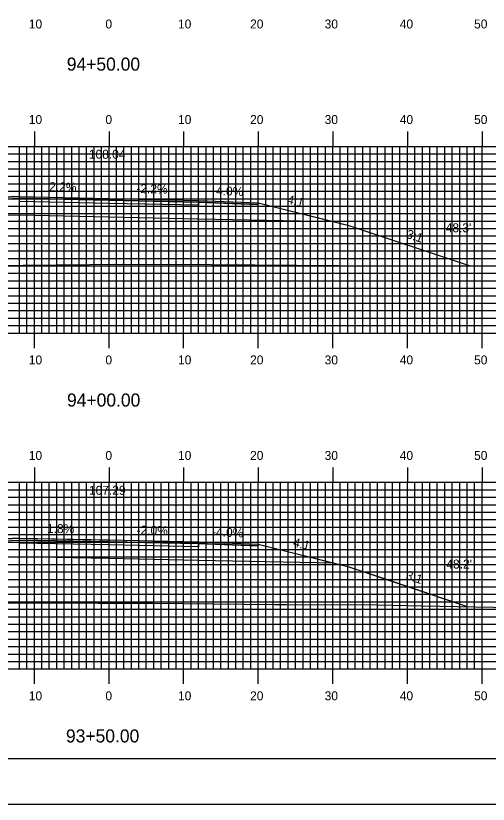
# Model space of a CAD drawing. Extents: x 1765333 to 1765676, y 442591 to 442811.
# Drawn here: x 1765485.9 to 1765549.2, y 442590.5 to 442696.2 of the extents above; entities that cross this region are included whole.
import ezdxf

# ---------------------------------------------------------------- set-up
doc = ezdxf.new("R2010")
doc.units = 0
for name, color, linetype in [('ANNOTATION', 7, 'Continuous'), ('BORDER', 7, 'Continuous'), ('D_Roadway_Centerline', 7, 'Continuous'), ('D_Roadway_Centerline_Text', 7, 'Continuous'), ('D_Roadway_Edge_Shoulder', 7, 'Continuous'), ('D_Roadway_Edge_TW', 7, 'Continuous'), ('D_Roadway_Pavement', 7, 'Continuous'), ('D_Roadway_SlopeLines', 7, 'Continuous'), ('D_Roadway_SubGrade', 7, 'Continuous'), ('D_Text_Standard', 7, 'Continuous'), ('H_V ANNOTATION', 7, 'Continuous'), ('MAJOR', 7, 'Continuous'), ('MINOR', 7, 'Continuous'), ('PLOT BOUNDARY', 7, 'Continuous'), ('S_Roadway_Centerline', 7, 'Continuous')]:
    doc.layers.add(name, color=color, linetype=linetype)

msp = doc.modelspace()

# ---------------------------------------------------------------- linework, layer by layer
at = {"layer": 'BORDER'}
msp.add_lwpolyline([(1765348.77, 442596.67), (1765668.77, 442596.67), (1765668.77, 442806.67), (1765348.77, 442806.67)], close=True, dxfattribs=at)
at = {"layer": 'D_Roadway_Centerline'}
for points in [[(1765447.79, 442662.46), (1765466.37, 442668.65), (1765466.37, 442668.65), (1765466.86, 442668.77), (1765468.2, 442669.11), (1765468.2, 442669.11), (1765473.59, 442670.45), (1765478.37, 442671.65), (1765478.37, 442671.65), (1765486.37, 442671.97), (1765486.38, 442671.97), (1765498.37, 442671.71), (1765510.37, 442671.44), (1765518.37, 442671.12), (1765518.37, 442671.12), (1765526.92, 442668.98), (1765528.55, 442668.58), (1765529.56, 442668.32), (1765530.37, 442668.12), (1765546.65, 442662.7), (1765546.65, 442662.7)], [(1765449.22, 442617.13), (1765449.22, 442617.13), (1765460.52, 442620.9), (1765466.36, 442622.84), (1765466.37, 442622.85), (1765466.37, 442622.85), (1765468.2, 442623.3), (1765468.2, 442623.3), (1765472.08, 442624.28), (1765478.37, 442625.85), (1765486.37, 442626.17), (1765497.05, 442625.98), (1765498.37, 442625.96), (1765510.36, 442625.72), (1765510.37, 442625.72), (1765518.36, 442625.4), (1765518.37, 442625.4), (1765528.54, 442622.85), (1765528.54, 442622.85), (1765528.96, 442622.75), (1765530.37, 442622.4), (1765535.39, 442620.72), (1765546.52, 442617.01)]]:
    msp.add_lwpolyline(points, dxfattribs=at)
at = {"layer": 'D_Roadway_Edge_Shoulder'}
for points in [[(1765486.37, 442671.97), (1765478.37, 442671.65), (1765478.37, 442671.4), (1765486.37, 442671.72)], [(1765510.37, 442671.44), (1765518.37, 442671.12), (1765518.37, 442670.87), (1765510.37, 442671.19)], [(1765486.37, 442626.17), (1765478.37, 442625.85), (1765478.37, 442625.6), (1765486.37, 442625.92)], [(1765510.37, 442625.72), (1765518.37, 442625.4), (1765518.37, 442625.15), (1765510.37, 442625.47)]]:
    msp.add_lwpolyline(points, close=True, dxfattribs=at)
at = {"layer": 'D_Roadway_Edge_TW'}
for points in [[(1765486.37, 442671.72), (1765486.37, 442671.97), (1765498.37, 442671.71), (1765510.37, 442671.44), (1765510.37, 442671.19), (1765498.37, 442671.46)], [(1765486.37, 442625.92), (1765486.37, 442626.17), (1765498.37, 442625.96), (1765510.37, 442625.72), (1765510.37, 442625.47), (1765498.37, 442625.71)]]:
    msp.add_lwpolyline(points, close=True, dxfattribs=at)
at = {"layer": 'D_Roadway_Pavement'}
for points in [[(1765486.37, 442671.3), (1765486.37, 442671.72), (1765498.37, 442671.46), (1765510.37, 442671.19), (1765510.37, 442670.78), (1765498.37, 442671.04)], [(1765486.37, 442625.5), (1765486.37, 442625.92), (1765498.37, 442625.71), (1765510.37, 442625.47), (1765510.37, 442625.05), (1765498.37, 442625.29)]]:
    msp.add_lwpolyline(points, close=True, dxfattribs=at)
at = {"layer": 'D_Roadway_SlopeLines'}
for points in [[(1765518.37, 442671.12), (1765530.37, 442668.12), (1765546.65, 442662.7)], [(1765518.37, 442625.4), (1765530.37, 442622.4), (1765546.52, 442617.01)]]:
    msp.add_lwpolyline(points, dxfattribs=at)
at = {"layer": 'D_Roadway_SubGrade'}
for points in [[(1765486.37, 442669.47), (1765468.2, 442669.11), (1765478.37, 442671.65), (1765478.37, 442671.4), (1765486.37, 442671.72), (1765498.37, 442671.46), (1765510.37, 442671.19), (1765518.37, 442670.87), (1765518.37, 442671.12), (1765528.55, 442668.58), (1765510.37, 442668.94), (1765498.37, 442669.21)], [(1765486.37, 442623.67), (1765468.2, 442623.3), (1765478.37, 442625.85), (1765478.37, 442625.6), (1765486.37, 442625.92), (1765498.37, 442625.71), (1765510.37, 442625.47), (1765518.37, 442625.15), (1765518.37, 442625.4), (1765528.54, 442622.85), (1765510.37, 442623.22), (1765498.37, 442623.46)]]:
    msp.add_lwpolyline(points, close=True, dxfattribs=at)
at = {"layer": 'MAJOR'}
for p, q in [((1765488.37, 442680.67), (1765488.37, 442678.67)), ((1765498.37, 442680.67), (1765498.37, 442678.67)), ((1765508.37, 442680.67), (1765508.37, 442678.67)), ((1765518.37, 442680.67), (1765518.37, 442678.67)), ((1765528.37, 442680.67), (1765528.37, 442678.67)), ((1765538.37, 442680.67), (1765538.37, 442678.67)), ((1765548.37, 442680.67), (1765548.37, 442678.67)), ((1765358.37, 442678.67), (1765638.37, 442678.67)), ((1765358.37, 442678.67), (1765638.37, 442678.67)), ((1765488.37, 442653.67), (1765488.37, 442678.67)), ((1765498.37, 442653.67), (1765498.37, 442678.67)), ((1765508.37, 442653.67), (1765508.37, 442678.67)), ((1765518.37, 442653.67), (1765518.37, 442678.67)), ((1765528.37, 442653.67), (1765528.37, 442678.67)), ((1765538.37, 442653.67), (1765538.37, 442678.67)), ((1765548.37, 442653.67), (1765548.37, 442678.67)), ((1765358.37, 442673.67), (1765638.37, 442673.67)), ((1765358.37, 442668.67), (1765638.37, 442668.67)), ((1765358.37, 442663.67), (1765638.37, 442663.67)), ((1765358.37, 442658.67), (1765638.37, 442658.67)), ((1765358.37, 442653.67), (1765638.37, 442653.67)), ((1765358.37, 442653.67), (1765638.37, 442653.67)), ((1765488.37, 442651.66), (1765488.37, 442653.67)), ((1765498.37, 442651.66), (1765498.37, 442653.67)), ((1765508.37, 442651.66), (1765508.37, 442653.67)), ((1765518.37, 442651.66), (1765518.37, 442653.67)), ((1765528.37, 442651.66), (1765528.37, 442653.67)), ((1765538.37, 442651.66), (1765538.37, 442653.67)), ((1765548.37, 442651.66), (1765548.37, 442653.67)), ((1765488.37, 442635.67), (1765488.37, 442633.67)), ((1765498.37, 442635.67), (1765498.37, 442633.67)), ((1765508.37, 442635.67), (1765508.37, 442633.67)), ((1765518.37, 442635.67), (1765518.37, 442633.67)), ((1765528.37, 442635.67), (1765528.37, 442633.67)), ((1765538.37, 442635.67), (1765538.37, 442633.67)), ((1765548.37, 442635.67), (1765548.37, 442633.67)), ((1765358.37, 442633.67), (1765638.37, 442633.67)), ((1765358.37, 442633.67), (1765638.37, 442633.67)), ((1765488.37, 442608.67), (1765488.37, 442633.67)), ((1765498.37, 442608.67), (1765498.37, 442633.67)), ((1765508.37, 442608.67), (1765508.37, 442633.67)), ((1765518.37, 442608.67), (1765518.37, 442633.67)), ((1765528.37, 442608.67), (1765528.37, 442633.67)), ((1765538.37, 442608.67), (1765538.37, 442633.67)), ((1765548.37, 442608.67), (1765548.37, 442633.67)), ((1765358.37, 442628.67), (1765638.37, 442628.67)), ((1765358.37, 442623.67), (1765638.37, 442623.67)), ((1765358.37, 442618.67), (1765638.37, 442618.67)), ((1765358.37, 442613.67), (1765638.37, 442613.67)), ((1765358.37, 442608.67), (1765638.37, 442608.67)), ((1765358.37, 442608.67), (1765638.37, 442608.67)), ((1765488.37, 442606.66), (1765488.37, 442608.67)), ((1765498.37, 442606.66), (1765498.37, 442608.67)), ((1765508.37, 442606.66), (1765508.37, 442608.67)), ((1765518.37, 442606.66), (1765518.37, 442608.67)), ((1765528.37, 442606.66), (1765528.37, 442608.67)), ((1765538.37, 442606.66), (1765538.37, 442608.67)), ((1765548.37, 442606.66), (1765548.37, 442608.67))]:
    msp.add_line(p, q, dxfattribs=at)
at = {"layer": 'MINOR'}
for p, q in [((1765486.37, 442653.67), (1765486.37, 442678.67)), ((1765487.37, 442653.67), (1765487.37, 442678.67)), ((1765489.37, 442653.67), (1765489.37, 442678.67)), ((1765490.37, 442653.67), (1765490.37, 442678.67)), ((1765491.37, 442653.67), (1765491.37, 442678.67)), ((1765492.37, 442653.67), (1765492.37, 442678.67)), ((1765493.37, 442653.67), (1765493.37, 442678.67)), ((1765494.37, 442653.67), (1765494.37, 442678.67)), ((1765495.37, 442653.67), (1765495.37, 442678.67)), ((1765496.37, 442653.67), (1765496.37, 442678.67)), ((1765497.37, 442653.67), (1765497.37, 442678.67)), ((1765499.37, 442653.67), (1765499.37, 442678.67)), ((1765500.37, 442653.67), (1765500.37, 442678.67)), ((1765501.37, 442653.67), (1765501.37, 442678.67)), ((1765502.37, 442653.67), (1765502.37, 442678.67)), ((1765503.37, 442653.67), (1765503.37, 442678.67)), ((1765504.37, 442653.67), (1765504.37, 442678.67)), ((1765505.37, 442653.67), (1765505.37, 442678.67)), ((1765506.37, 442653.67), (1765506.37, 442678.67)), ((1765507.37, 442653.67), (1765507.37, 442678.67)), ((1765509.37, 442653.67), (1765509.37, 442678.67)), ((1765510.37, 442653.67), (1765510.37, 442678.67)), ((1765511.37, 442653.67), (1765511.37, 442678.67)), ((1765512.37, 442653.67), (1765512.37, 442678.67)), ((1765513.37, 442653.67), (1765513.37, 442678.67)), ((1765514.37, 442653.67), (1765514.37, 442678.67)), ((1765515.37, 442653.67), (1765515.37, 442678.67)), ((1765516.37, 442653.67), (1765516.37, 442678.67)), ((1765517.37, 442653.67), (1765517.37, 442678.67)), ((1765519.37, 442653.67), (1765519.37, 442678.67)), ((1765520.37, 442653.67), (1765520.37, 442678.67)), ((1765521.37, 442653.67), (1765521.37, 442678.67)), ((1765522.37, 442653.67), (1765522.37, 442678.67)), ((1765523.37, 442653.67), (1765523.37, 442678.67)), ((1765524.37, 442653.67), (1765524.37, 442678.67)), ((1765525.37, 442653.67), (1765525.37, 442678.67)), ((1765526.37, 442653.67), (1765526.37, 442678.67)), ((1765527.37, 442653.67), (1765527.37, 442678.67)), ((1765529.37, 442653.67), (1765529.37, 442678.67)), ((1765530.37, 442653.67), (1765530.37, 442678.67)), ((1765531.37, 442653.67), (1765531.37, 442678.67)), ((1765532.37, 442653.67), (1765532.37, 442678.67)), ((1765533.37, 442653.67), (1765533.37, 442678.67)), ((1765534.37, 442653.67), (1765534.37, 442678.67)), ((1765535.37, 442653.67), (1765535.37, 442678.67)), ((1765536.37, 442653.67), (1765536.37, 442678.67)), ((1765537.37, 442653.67), (1765537.37, 442678.67)), ((1765539.37, 442653.67), (1765539.37, 442678.67)), ((1765540.37, 442653.67), (1765540.37, 442678.67)), ((1765541.37, 442653.67), (1765541.37, 442678.67)), ((1765542.37, 442653.67), (1765542.37, 442678.67)), ((1765543.37, 442653.67), (1765543.37, 442678.67)), ((1765544.37, 442653.67), (1765544.37, 442678.67)), ((1765545.37, 442653.67), (1765545.37, 442678.67)), ((1765546.37, 442653.67), (1765546.37, 442678.67)), ((1765547.37, 442653.67), (1765547.37, 442678.67)), ((1765358.37, 442677.67), (1765638.37, 442677.67)), ((1765358.37, 442676.67), (1765638.37, 442676.67)), ((1765358.37, 442675.67), (1765638.37, 442675.67)), ((1765358.37, 442674.67), (1765638.37, 442674.67)), ((1765358.37, 442672.67), (1765638.37, 442672.67)), ((1765358.37, 442671.67), (1765638.37, 442671.67)), ((1765358.37, 442670.67), (1765638.37, 442670.67)), ((1765358.37, 442669.67), (1765638.37, 442669.67)), ((1765358.37, 442667.67), (1765638.37, 442667.67)), ((1765358.37, 442666.67), (1765638.37, 442666.67)), ((1765358.37, 442665.67), (1765638.37, 442665.67)), ((1765358.37, 442664.67), (1765638.37, 442664.67)), ((1765358.37, 442662.67), (1765638.37, 442662.67)), ((1765358.37, 442661.67), (1765638.37, 442661.67)), ((1765358.37, 442660.67), (1765638.37, 442660.67)), ((1765358.37, 442659.67), (1765638.37, 442659.67)), ((1765358.37, 442657.67), (1765638.37, 442657.67)), ((1765358.37, 442656.67), (1765638.37, 442656.67)), ((1765358.37, 442655.67), (1765638.37, 442655.67)), ((1765358.37, 442654.67), (1765638.37, 442654.67)), ((1765486.37, 442608.67), (1765486.37, 442633.67)), ((1765487.37, 442608.67), (1765487.37, 442633.67)), ((1765489.37, 442608.67), (1765489.37, 442633.67)), ((1765490.37, 442608.67), (1765490.37, 442633.67)), ((1765491.37, 442608.67), (1765491.37, 442633.67)), ((1765492.37, 442608.67), (1765492.37, 442633.67)), ((1765493.37, 442608.67), (1765493.37, 442633.67)), ((1765494.37, 442608.67), (1765494.37, 442633.67)), ((1765495.37, 442608.67), (1765495.37, 442633.67)), ((1765496.37, 442608.67), (1765496.37, 442633.67)), ((1765497.37, 442608.67), (1765497.37, 442633.67)), ((1765499.37, 442608.67), (1765499.37, 442633.67)), ((1765500.37, 442608.67), (1765500.37, 442633.67)), ((1765501.37, 442608.67), (1765501.37, 442633.67)), ((1765502.37, 442608.67), (1765502.37, 442633.67)), ((1765503.37, 442608.67), (1765503.37, 442633.67)), ((1765504.37, 442608.67), (1765504.37, 442633.67)), ((1765505.37, 442608.67), (1765505.37, 442633.67)), ((1765506.37, 442608.67), (1765506.37, 442633.67)), ((1765507.37, 442608.67), (1765507.37, 442633.67)), ((1765509.37, 442608.67), (1765509.37, 442633.67)), ((1765510.37, 442608.67), (1765510.37, 442633.67)), ((1765511.37, 442608.67), (1765511.37, 442633.67)), ((1765512.37, 442608.67), (1765512.37, 442633.67)), ((1765513.37, 442608.67), (1765513.37, 442633.67)), ((1765514.37, 442608.67), (1765514.37, 442633.67)), ((1765515.37, 442608.67), (1765515.37, 442633.67)), ((1765516.37, 442608.67), (1765516.37, 442633.67)), ((1765517.37, 442608.67), (1765517.37, 442633.67)), ((1765519.37, 442608.67), (1765519.37, 442633.67)), ((1765520.37, 442608.67), (1765520.37, 442633.67)), ((1765521.37, 442608.67), (1765521.37, 442633.67)), ((1765522.37, 442608.67), (1765522.37, 442633.67)), ((1765523.37, 442608.67), (1765523.37, 442633.67)), ((1765524.37, 442608.67), (1765524.37, 442633.67)), ((1765525.37, 442608.67), (1765525.37, 442633.67)), ((1765526.37, 442608.67), (1765526.37, 442633.67)), ((1765527.37, 442608.67), (1765527.37, 442633.67)), ((1765529.37, 442608.67), (1765529.37, 442633.67)), ((1765530.37, 442608.67), (1765530.37, 442633.67)), ((1765531.37, 442608.67), (1765531.37, 442633.67)), ((1765532.37, 442608.67), (1765532.37, 442633.67)), ((1765533.37, 442608.67), (1765533.37, 442633.67)), ((1765534.37, 442608.67), (1765534.37, 442633.67)), ((1765535.37, 442608.67), (1765535.37, 442633.67)), ((1765536.37, 442608.67), (1765536.37, 442633.67)), ((1765537.37, 442608.67), (1765537.37, 442633.67)), ((1765539.37, 442608.67), (1765539.37, 442633.67)), ((1765540.37, 442608.67), (1765540.37, 442633.67)), ((1765541.37, 442608.67), (1765541.37, 442633.67)), ((1765542.37, 442608.67), (1765542.37, 442633.67)), ((1765543.37, 442608.67), (1765543.37, 442633.67)), ((1765544.37, 442608.67), (1765544.37, 442633.67)), ((1765545.37, 442608.67), (1765545.37, 442633.67)), ((1765546.37, 442608.67), (1765546.37, 442633.67)), ((1765547.37, 442608.67), (1765547.37, 442633.67)), ((1765358.37, 442632.67), (1765638.37, 442632.67)), ((1765358.37, 442631.67), (1765638.37, 442631.67)), ((1765358.37, 442630.67), (1765638.37, 442630.67)), ((1765358.37, 442629.67), (1765638.37, 442629.67)), ((1765358.37, 442627.67), (1765638.37, 442627.67)), ((1765358.37, 442626.67), (1765638.37, 442626.67)), ((1765358.37, 442625.67), (1765638.37, 442625.67)), ((1765358.37, 442624.67), (1765638.37, 442624.67)), ((1765358.37, 442622.67), (1765638.37, 442622.67)), ((1765358.37, 442621.67), (1765638.37, 442621.67)), ((1765358.37, 442620.67), (1765638.37, 442620.67)), ((1765358.37, 442619.67), (1765638.37, 442619.67)), ((1765358.37, 442617.67), (1765638.37, 442617.67)), ((1765358.37, 442616.67), (1765638.37, 442616.67)), ((1765358.37, 442615.67), (1765638.37, 442615.67)), ((1765358.37, 442614.67), (1765638.37, 442614.67)), ((1765358.37, 442612.67), (1765638.37, 442612.67)), ((1765358.37, 442611.67), (1765638.37, 442611.67)), ((1765358.37, 442610.67), (1765638.37, 442610.67)), ((1765358.37, 442609.67), (1765638.37, 442609.67))]:
    msp.add_line(p, q, dxfattribs=at)
at = {"layer": 'PLOT BOUNDARY'}
msp.add_lwpolyline([(1765332.58, 442590.55), (1765672.58, 442590.55), (1765672.58, 442810.55), (1765332.58, 442810.55)], close=True, dxfattribs=at)
at = {"layer": 'S_Roadway_Centerline'}
for points in [[(1765431.28, 442662.36), (1765446.18, 442662.44), (1765453.89, 442662.51), (1765463.96, 442662.67), (1765466.53, 442662.72), (1765471.86, 442662.77), (1765475.74, 442662.69), (1765480.11, 442662.61), (1765480.14, 442662.69), (1765482.24, 442662.72), (1765491.42, 442662.81), (1765500.11, 442662.88), (1765512.06, 442662.84), (1765516.08, 442662.8), (1765517.93, 442662.79), (1765529.11, 442662.71), (1765535.88, 442662.67), (1765552.97, 442662.71)], [(1765439, 442617.02), (1765447.02, 442617.11), (1765450.46, 442617.14), (1765463.23, 442617.26), (1765466.88, 442617.28), (1765467.84, 442617.25), (1765469.61, 442617.31), (1765474.73, 442617.31), (1765476.73, 442617.31), (1765476.84, 442617.32), (1765480.58, 442617.43), (1765486.46, 442617.52), (1765496.94, 442617.5), (1765504.18, 442617.48), (1765520.59, 442617.3), (1765522.1, 442617.31), (1765534.42, 442617.26), (1765540.25, 442617.13), (1765554.75, 442616.85)]]:
    msp.add_lwpolyline(points, dxfattribs=at)

# ---------------------------------------------------------------- texts
at = {"layer": 'ANNOTATION'}
for s, rotation, p in [('2.2%', 358.7397, (1765490.34, 442672.68)), ('-2.2%', 358.7397, (1765502.02, 442672.43)), ('-4.0%', 357.7094, (1765512.16, 442672.17)), ('4:1', 345.962, (1765522.15, 442671.04)), ('3:1', 341.5633, (1765538.11, 442666.45)), ('1.8%', 358.9879, (1765490.05, 442626.9)), ('-2.0%', 358.8542, (1765502.05, 442626.68)), ('-4.0%', 357.7094, (1765512.16, 442626.45)), ('4:1', 345.9611, (1765522.96, 442625.11)), ('3:1', 341.564, (1765538.05, 442620.74))]:
    msp.add_text(s, height=1.2, rotation=rotation, dxfattribs=at).set_placement(p)
at = {"layer": 'D_Roadway_Centerline'}
for s, p in [('C', (1765498.37, 442671.71)), ('L', (1765498.37, 442671.7)), ('C', (1765498.37, 442625.96)), ('L', (1765498.37, 442625.95))]:
    msp.add_text(s, height=0.0146, dxfattribs=at).set_placement(p)
at = {"layer": 'D_Roadway_Centerline_Text'}
for s, p in [('108.04', (1765495.67, 442677.02)), ('107.29', (1765495.68, 442632))]:
    msp.add_text(s, height=1.2, dxfattribs=at).set_placement(p)
at = {"layer": 'D_Text_Standard'}
for s, p in [("48.3'", (1765543.5, 442667.17)), ("48.2'", (1765543.58, 442622.12))]:
    msp.add_text(s, height=1.2, dxfattribs=at).set_placement(p)
at = {"layer": 'H_V ANNOTATION'}
for s, height, p in [('10', 1.2, (1765487.62, 442694.47)), ('0', 1.2, (1765497.89, 442694.47)), ('10', 1.2, (1765507.62, 442694.47)), ('20', 1.2, (1765517.28, 442694.47)), ('30', 1.2, (1765527.27, 442694.47)), ('40', 1.2, (1765537.34, 442694.47)), ('50', 1.2, (1765547.3, 442694.47)), ('94+50.00', 1.75, (1765492.71, 442688.82)), ('10', 1.2, (1765487.62, 442681.67)), ('0', 1.2, (1765497.89, 442681.67)), ('10', 1.2, (1765507.62, 442681.67)), ('20', 1.2, (1765517.28, 442681.67)), ('30', 1.2, (1765527.27, 442681.67)), ('40', 1.2, (1765537.34, 442681.67)), ('50', 1.2, (1765547.3, 442681.67)), ('10', 1.2, (1765487.62, 442649.47)), ('0', 1.2, (1765497.89, 442649.47)), ('10', 1.2, (1765507.62, 442649.47)), ('20', 1.2, (1765517.28, 442649.47)), ('30', 1.2, (1765527.27, 442649.47)), ('40', 1.2, (1765537.34, 442649.47)), ('50', 1.2, (1765547.3, 442649.47)), ('94+00.00', 1.75, (1765492.74, 442643.82)), ('10', 1.2, (1765487.62, 442636.67)), ('0', 1.2, (1765497.89, 442636.67)), ('10', 1.2, (1765507.62, 442636.67)), ('20', 1.2, (1765517.28, 442636.67)), ('30', 1.2, (1765527.27, 442636.67)), ('40', 1.2, (1765537.34, 442636.67)), ('50', 1.2, (1765547.3, 442636.67)), ('10', 1.2, (1765487.62, 442604.47)), ('0', 1.2, (1765497.89, 442604.47)), ('10', 1.2, (1765507.62, 442604.47)), ('20', 1.2, (1765517.28, 442604.47)), ('30', 1.2, (1765527.27, 442604.47)), ('40', 1.2, (1765537.34, 442604.47)), ('50', 1.2, (1765547.3, 442604.47)), ('93+50.00', 1.75, (1765492.6, 442598.82))]:
    msp.add_text(s, height=height, dxfattribs=at).set_placement(p)

doc.saveas('drawing.dxf')
